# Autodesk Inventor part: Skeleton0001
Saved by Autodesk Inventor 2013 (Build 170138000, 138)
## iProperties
Created: 2009-11
Part Number: Skeleton0001
Document SubType Name: Modeling
Designer: pokornp
Density: 1 g/cm^3
Material: Generic
_SkeletonDoc: Frame Skeleton File
_Version: 15.0.0
Author: pokornp
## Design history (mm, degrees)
sketch "Reference Skeleton"
